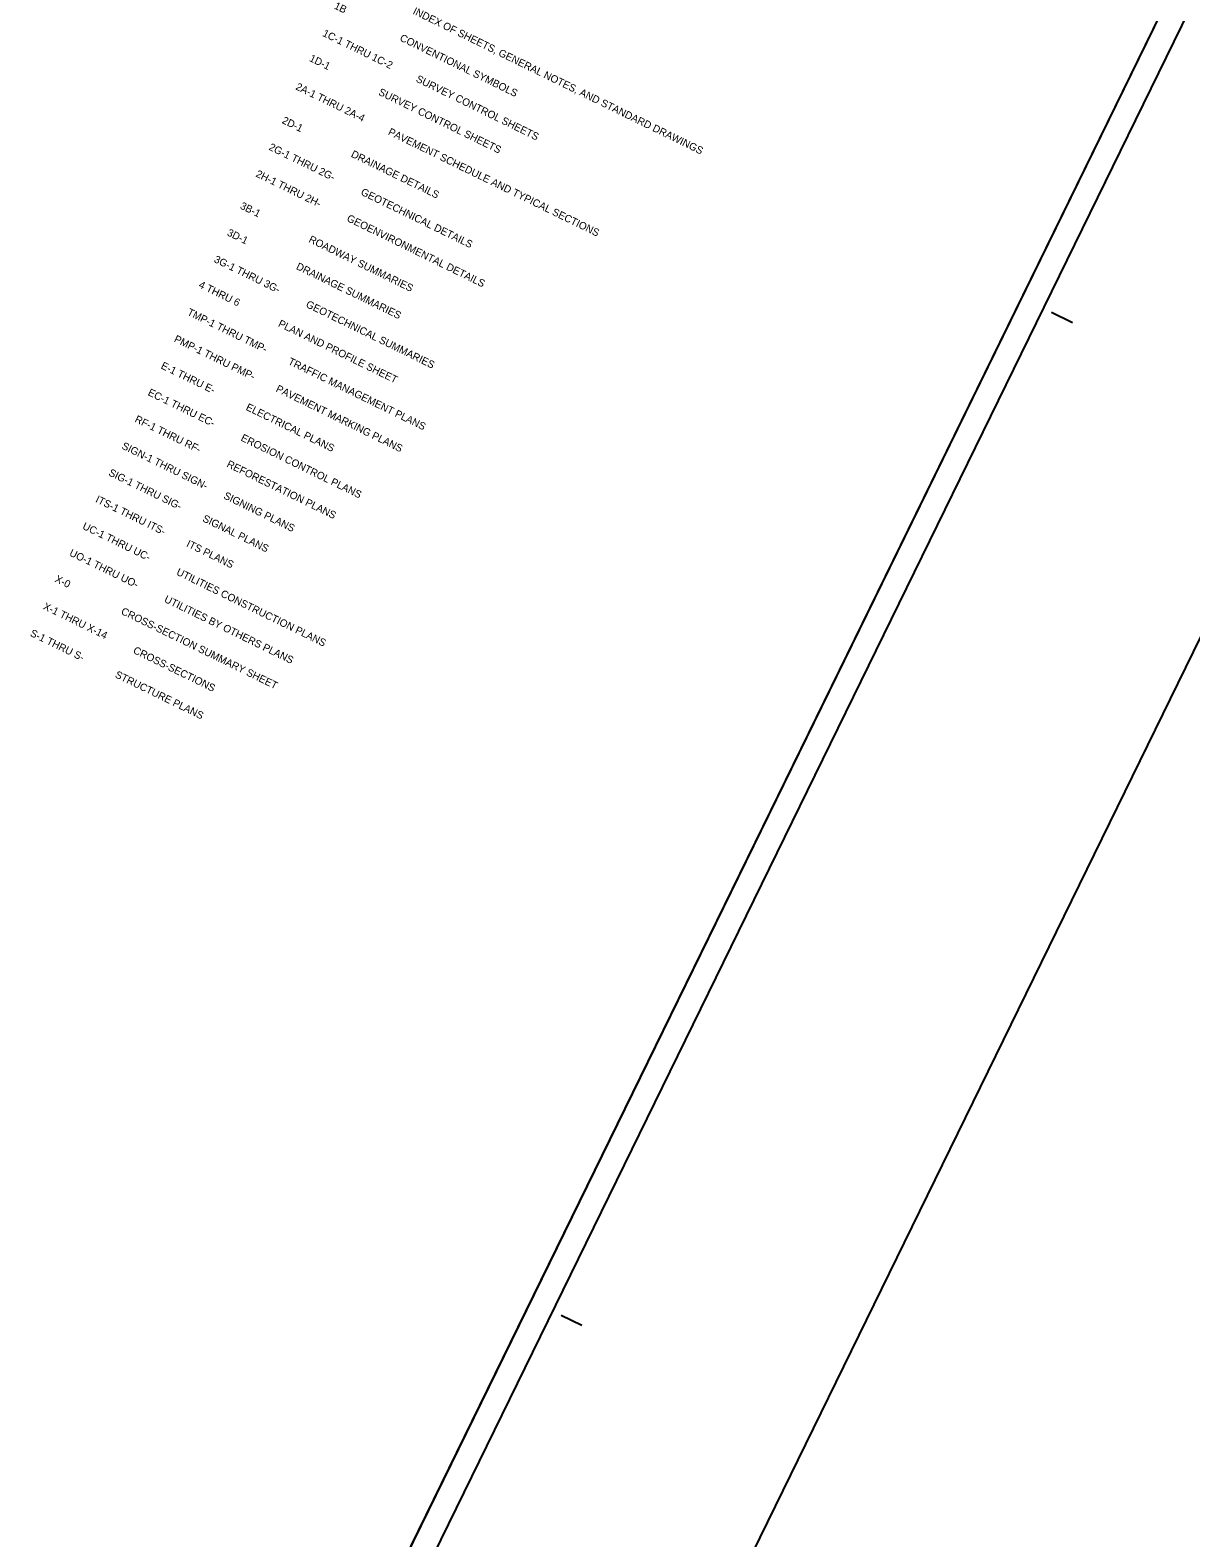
# Model space of a CAD drawing. Extents: x 1517888 to 1526099, y 633375 to 640181.
# Drawn here: x 1518813 to 1520060, y 635049 to 636669 of the extents above; entities that cross this region are included whole.
import ezdxf

# ---------------------------------------------------------------- set-up
doc = ezdxf.new("R2010")
doc.units = 0
for name, color, linetype in [('Sheet Cutting Line CELL', 7, 'Continuous'), ('Sheet Data Text CELL', 7, 'Continuous'), ('Sheet Plan CELL', 7, 'Continuous'), ('Sheet Plot Border Inside CELL', 7, 'Continuous'), ('Sheet Plot Border Outside CELL', 7, 'Continuous')]:
    doc.layers.add(name, color=color, linetype=linetype)

msp = doc.modelspace()

# ---------------------------------------------------------------- linework, layer by layer
at = {"layer": 'Sheet Cutting Line CELL'}
msp.add_line((1520093.5, 636822.1), (1519131.3, 634854.8), dxfattribs=at)
at = {"layer": 'Sheet Plan CELL'}
for p, q in [((1519910.5, 636366.1), (1519933, 636355.1)), ((1519383.3, 635288.1), (1519405.8, 635277.1))]:
    msp.add_line(p, q, dxfattribs=at)
msp.add_lwpolyline([(1523067.8, 635317.3), (1520372.9, 636635.4), (1519450.2, 634748.9), (1522145.2, 633430.8)], close=True, dxfattribs=at)
at = {"layer": 'Sheet Plot Border Inside CELL'}
msp.add_lwpolyline([(1519172.2, 634879.3), (1522165.4, 633415.4), (1523092.5, 635310.8), (1520099.3, 636774.7)], close=True, dxfattribs=at)
at = {"layer": 'Sheet Plot Border Outside CELL'}
msp.add_lwpolyline([(1519131.3, 634854.8), (1522155.9, 633375.5), (1523118.1, 635342.8), (1520093.5, 636822.1)], close=True, dxfattribs=at)

# ---------------------------------------------------------------- texts
at = {"layer": 'Sheet Data Text CELL'}
for s, p in [('1A                      INDEX OF SHEETS, GENERAL NOTES, AND STANDARD DRAWINGS', (1519152.9, 636721.7)), ('1B                      CONVENTIONAL SYMBOLS ', (1519138.8, 636692.9)), ('1C-1 THRU 1C-2          SURVEY CONTROL SHEETS', (1519126.3, 636663.4)), ('1D-1                    SURVEY CONTROL SHEETS', (1519112.1, 636636.5)), ('2A-1 THRU 2A-4          PAVEMENT SCHEDULE AND TYPICAL SECTIONS', (1519097.4, 636606)), ('2D-1                    DRAINAGE DETAILS', (1519082.7, 636569.8)), ('2G-1 THRU 2G-           GEOTECHNICAL DETAILS', (1519068.6, 636541.1)), ('2H-1 THRU 2H-           GEOENVIRONMENTAL DETAILS', (1519054.6, 636512.3)), ('3B-1                    ROADWAY SUMMARIES', (1519037.7, 636477.9)), ('3D-1                    DRAINAGE SUMMARIES', (1519023.7, 636449.1)), ('3G-1 THRU 3G-           GEOTECHNICAL SUMMARIES', (1519009.6, 636420.4)), ('4 THRU 6                PLAN AND PROFILE SHEET', (1518993.2, 636393.1)), ('TMP-1 THRU TMP-         TRAFFIC MANAGEMENT PLANS', (1518980.8, 636363.6)), ('PMP-1 THRU PMP-         PAVEMENT MARKING PLANS', (1518966.7, 636334.8)), ('E-1 THRU E-             ELECTRICAL PLANS', (1518952.6, 636306.1)), ('EC-1 THRU EC-           EROSION CONTROL PLANS', (1518938.6, 636277.3)), ('RF-1 THRU RF-           REFORESTATION PLANS', (1518924.5, 636248.6)), ('SIGN-1 THRU SIGN-       SIGNING PLANS', (1518910.5, 636219.8)), ('SIG-1 THRU SIG-         SIGNAL PLANS', (1518896.4, 636191.1)), ('ITS-1 THRU ITS-         ITS PLANS', (1518882.3, 636162.4)), ('UC-1 THRU UC-           UTILITIES CONSTRUCTION PLANS', (1518868.3, 636133.6)), ('UO-1 THRU UO-           UTILITIES BY OTHERS PLANS', (1518854.2, 636104.9)), ('X-0                     CROSS-SECTION SUMMARY SHEET', (1518838.7, 636076.8)), ('X-1 THRU X-14           CROSS-SECTIONS', (1518826.1, 636047.4)), ('S-1 THRU S-             STRUCTURE PLANS', (1518812, 636018.6))]:
    msp.add_text(s, height=8, rotation=333.9377, dxfattribs=at).set_placement(p)

doc.saveas('drawing.dxf')
